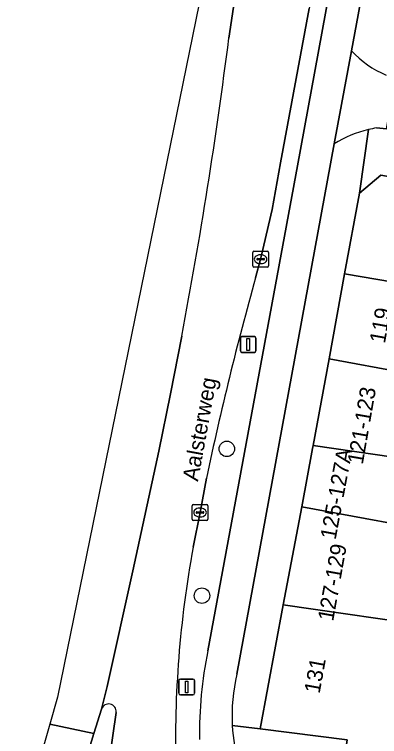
# Model space of a CAD drawing. Extents: x 161838 to 162344, y 381620 to 382160.
# Drawn here: x 161845.08 to 161868.19, y 381676.84 to 381722.46 of the extents above; entities that cross this region are included whole.
import ezdxf

# ---------------------------------------------------------------- set-up
doc = ezdxf.new("R2010")
doc.units = 0
for name, color, linetype in [('IMGEO_Berm_open', 7, 'Continuous'), ('IMGEO_Boom', 7, 'Continuous'), ('IMGEO_Fietspad_gesloten', 7, 'Continuous'), ('IMGEO_Kolk', 7, 'Continuous'), ('IMGEO_Lichtmast', 7, 'Continuous'), ('IMGEO_Openbare_ruimte_label', 7, 'Continuous'), ('IMGEO_OVBaan_gesloten', 7, 'Continuous'), ('IMGEO_Pand', 7, 'Continuous'), ('IMGEO_Pand_nummerreeks', 7, 'Continuous'), ('IMGEO_Rijbaan_lokaal_gesloten', 7, 'Continuous'), ('IMGEO_Rijbaan_lokaal_open', 7, 'Continuous'), ('IMGEO_Verkeerseiland_open', 7, 'Continuous'), ('IMGEO_Voetpad_open', 7, 'Continuous')]:
    doc.layers.add(name, color=color, linetype=linetype)

msp = doc.modelspace()

# ---------------------------------------------------------------- linework, layer by layer
at = {"layer": 'IMGEO_Berm_open'}
for points in [[(161857.316, 381682.246), (161862.987, 381712.892), (161864.774, 381722.548), (161869.854, 381750), (161870.207, 381751.91), (161895.081, 381884.229), (161897.858, 381899.101)], [(161867.182, 381741.481), (161867.15, 381741.313), (161863.721, 381722.825), (161861.927, 381713.087), (161861.385, 381710.143), (161860.718, 381707.24), (161860.66, 381706.996), (161860.336, 381705.821)], [(161857.237, 381693.169), (161856.828, 381690.992), (161856.388, 381688.799)]]:
    msp.add_lwpolyline(points, dxfattribs=at)
for centre, radius, start, end in [((162053.993, 381651.681), 201.083, 164.38075, 168.09298), ((161923.078, 381676.552), 67.805, 169.59407, 181.46627), ((161883.604, 381676.943), 26.817, 168.5945, 180.6234)]:
    msp.add_arc(centre, radius, start, end, dxfattribs=at)
at = {"layer": 'IMGEO_Boom'}
for centre in [(161858.521, 381695.01), (161856.948, 381685.734)]:
    msp.add_circle(centre, 0.489, dxfattribs=at)
at = {"layer": 'IMGEO_Fietspad_gesloten'}
for points in [[(161926.346, 382051.921), (161921.558, 382026.031), (161916.698, 382000), (161897.858, 381899.101), (161895.081, 381884.229), (161870.207, 381751.91), (161869.854, 381750), (161864.774, 381722.548), (161862.987, 381712.892), (161857.316, 381682.246)], [(161859.158, 381680.785), (161865.321, 381714.277), (161866.402, 381720.165), (161871.936, 381750), (161872.236, 381751.615), (161897.095, 381883.929)]]:
    msp.add_lwpolyline(points, dxfattribs=at)
for centre, radius, start, end in [((161883.604, 381676.943), 26.817, 168.5945, 180.6234), ((161870.183, 381678.165), 11.332, 166.6322, 183.1415), ((161870.106, 381678.174), 11.256, 183.2077, 196.1764)]:
    msp.add_arc(centre, radius, start, end, dxfattribs=at)
at = {"layer": 'IMGEO_Kolk'}
for p, q in [((161860.16, 381706.569), (161860.16, 381707.421)), ((161860.235, 381707.495), (161861.087, 381707.495)), ((161861.161, 381707.421), (161861.161, 381706.569)), ((161860.419, 381706.989), (161860.419, 381707.001)), ((161860.857, 381706.952), (161860.459, 381706.952)), ((161860.462, 381707.038), (161860.86, 381707.038)), ((161860.648, 381707.275), (161860.673, 381707.275)), ((161860.903, 381707.001), (161860.903, 381706.989)), ((161861.087, 381706.495), (161860.235, 381706.495)), ((161860.671, 381706.715), (161860.646, 381706.715)), ((161856.328, 381690.566), (161856.328, 381691.418)), ((161856.403, 381691.492), (161857.255, 381691.492)), ((161857.329, 381691.418), (161857.329, 381690.566)), ((161856.587, 381690.986), (161856.587, 381690.998)), ((161857.025, 381690.949), (161856.627, 381690.949)), ((161856.63, 381691.035), (161857.028, 381691.035)), ((161856.816, 381691.272), (161856.841, 381691.272)), ((161857.071, 381690.998), (161857.071, 381690.986)), ((161857.255, 381690.492), (161856.403, 381690.492)), ((161856.839, 381690.712), (161856.814, 381690.712))]:
    msp.add_line(p, q, dxfattribs=at)
for points in [[(161860.16, 381706.569), (161860.16, 381707.421)], [(161860.235, 381707.495), (161861.087, 381707.495)], [(161861.161, 381707.421), (161861.161, 381706.569)], [(161861.087, 381706.495), (161860.235, 381706.495)], [(161856.328, 381690.566), (161856.328, 381691.418)], [(161856.403, 381691.492), (161857.255, 381691.492)], [(161857.329, 381691.418), (161857.329, 381690.566)], [(161857.255, 381690.492), (161856.403, 381690.492)]]:
    msp.add_lwpolyline(points, dxfattribs=at)
for centre, radius, start, end in [((161860.237, 381707.419), 0.0765, 91.552, 178.448), ((161860.237, 381707.419), 0.0765, 91.552, 178.448), ((161861.085, 381707.419), 0.0765, 1.552, 88.448), ((161861.085, 381707.419), 0.0765, 1.552, 88.448), ((161860.459, 381706.998), 0.0403, 85.8775, 175.7526), ((161860.456, 381706.988), 0.0366, 178.938, 274.7102), ((161860.86, 381706.995), 0.043, 264.8664, 352.4533), ((161860.864, 381707), 0.0386, 1.7309, 96.639), ((161860.237, 381706.571), 0.0765, 181.552, 268.448), ((161860.237, 381706.571), 0.0765, 181.552, 268.448), ((161861.085, 381706.571), 0.0765, 271.552, 358.448), ((161861.085, 381706.571), 0.0765, 271.552, 358.448), ((161856.405, 381691.416), 0.0765, 91.552, 178.448), ((161856.405, 381691.416), 0.0765, 91.552, 178.448), ((161857.253, 381691.416), 0.0765, 1.552, 88.448), ((161857.253, 381691.416), 0.0765, 1.552, 88.448), ((161856.627, 381690.995), 0.0403, 85.8775, 175.7526), ((161856.624, 381690.985), 0.0366, 178.938, 274.7102), ((161857.028, 381690.992), 0.043, 264.8664, 352.4533), ((161857.032, 381690.997), 0.0386, 1.7309, 96.639), ((161856.405, 381690.568), 0.0765, 181.552, 268.448), ((161856.405, 381690.568), 0.0765, 181.552, 268.448), ((161857.253, 381690.568), 0.0765, 271.552, 358.448), ((161857.253, 381690.568), 0.0765, 271.552, 358.448)]:
    msp.add_arc(centre, radius, start, end, dxfattribs=at)
for centre, major_axis, ratio, start_param, end_param in [((161860.647, 381706.995), (-0.387, 0.002), 0.722429, 4.712389, 7.853982), ((161860.672, 381706.995), (-0.39, 0.002), 0.717154, 1.570796, 4.712389), ((161856.815, 381690.992), (-0.387, 0.002), 0.722429, 4.712389, 7.853982), ((161856.84, 381690.992), (-0.39, 0.002), 0.717154, 1.570796, 4.712389)]:
    msp.add_ellipse(centre, major_axis=major_axis, ratio=ratio, start_param=start_param, end_param=end_param, dxfattribs=at)
at = {"layer": 'IMGEO_Lichtmast'}
for p, q in [((161859.376, 381701.208), (161859.376, 381702.008)), ((161859.376, 381702.008), (161859.376, 381701.208)), ((161859.476, 381702.108), (161860.266, 381702.108)), ((161860.266, 381702.108), (161859.476, 381702.108)), ((161860.366, 381702.008), (161860.366, 381701.208)), ((161860.366, 381701.208), (161860.366, 381702.008)), ((161860.266, 381701.108), (161859.476, 381701.108)), ((161859.476, 381701.108), (161860.266, 381701.108)), ((161855.585, 381680.469), (161856.375, 381680.469)), ((161856.375, 381680.469), (161855.585, 381680.469)), ((161855.485, 381679.569), (161855.485, 381680.369)), ((161855.485, 381680.369), (161855.485, 381679.569)), ((161856.475, 381680.369), (161856.475, 381679.569)), ((161856.475, 381679.569), (161856.475, 381680.369)), ((161856.375, 381679.469), (161855.585, 381679.469)), ((161855.585, 381679.469), (161856.375, 381679.469))]:
    msp.add_line(p, q, dxfattribs=at)
for points in [[(161859.796, 381701.983), (161859.946, 381701.983), (161859.946, 381701.233), (161859.796, 381701.233), (161859.796, 381701.983)], [(161855.905, 381680.344), (161856.055, 381680.344), (161856.055, 381679.594), (161855.905, 381679.594), (161855.905, 381680.344)]]:
    msp.add_lwpolyline(points, dxfattribs=at)
for centre, start, end in [((161859.476, 381702.008), 90, 180), ((161859.476, 381702.008), 90, 180), ((161860.266, 381702.008), 0, 90), ((161860.266, 381702.008), 360, 90), ((161859.476, 381701.208), 180, 270), ((161859.476, 381701.208), 180, 270), ((161860.266, 381701.208), 270, 0), ((161860.266, 381701.208), 270, 0), ((161855.585, 381680.369), 90, 180), ((161855.585, 381680.369), 90, 180), ((161856.375, 381680.369), 0, 90), ((161856.375, 381680.369), 360, 90), ((161855.585, 381679.569), 180, 270), ((161855.585, 381679.569), 180, 270), ((161856.375, 381679.569), 270, 0), ((161856.375, 381679.569), 270, 0)]:
    msp.add_arc(centre, 0.1, start, end, dxfattribs=at)
at = {"layer": 'IMGEO_OVBaan_gesloten'}
for points in [[(161858.651, 381720.96), (161859.425, 381726.158), (161861.132, 381736.231), (161869.606, 381781.344), (161897.211, 381928.16), (161915.531, 382025.949), (161915.767, 382027.092), (161920.812, 382054.098), (161923.657, 382069.694), (161925.944, 382081.248), (161931.886, 382108.929), (161933.831, 382119.131), (161934.302, 382121.796), (161934.443, 382123.117), (161933.101, 382124.399), (161916.93, 382035.129), (161911.481, 382007.357), (161883.773, 381866.122), (161869.795, 381786.79), (161847.814, 381679.325), (161847.327, 381677.629)], [(161847.327, 381677.629), (161850.099, 381677.022), (161850.6, 381678.563), (161850.947, 381680.009), (161852.565, 381687.299), (161854.222, 381694.86), (161854.959, 381698.492), (161855.668, 381702.138)]]:
    msp.add_lwpolyline(points, dxfattribs=at)
msp.add_arc((161552.98, 381759.757), 308.123, 349.22229, 352.7665, dxfattribs=at)
at = {"layer": 'IMGEO_Pand'}
for points in [[(161865.976, 381706.071), (161875.017, 381704.529), (161884.134, 381702.846), (161883.394, 381698.839), (161888.293, 381698.163), (161889.03, 381703.608), (161889.701, 381708.562), (161868.259, 381712.301), (161866.911, 381711.167)], [(161864.991, 381700.701), (161879.355, 381698.049), (161879.861, 381700.795), (161874.51, 381701.783), (161875.017, 381704.529), (161865.976, 381706.071)], [(161879.355, 381698.049), (161864.991, 381700.701), (161863.987, 381695.233), (161874.156, 381693.76), (161874.552, 381695.908), (161879.868, 381695.095), (161880.378, 381697.86)], [(161874.156, 381693.76), (161863.987, 381695.233), (161863.949, 381695.025), (161863.26, 381691.359), (161882.969, 381687.722), (161883.096, 381688.415), (161883.357, 381689.827), (161877.499, 381690.634), (161877.82, 381692.85), (161875.023, 381693.255), (161874.094, 381693.426)], [(161892.652, 381687.039), (161883.096, 381688.415), (161882.969, 381687.722), (161863.26, 381691.359), (161862.095, 381685.158), (161872.016, 381683.722), (161872.074, 381684.036), (161876.798, 381683.292), (161882.189, 381682.256), (161885.412, 381681.832), (161886.558, 381681.681), (161890.01, 381681.227), (161891.585, 381681.02)], [(161886.558, 381681.681), (161885.412, 381681.832), (161882.189, 381682.256), (161876.798, 381683.292), (161872.074, 381684.036), (161872.016, 381683.722), (161862.095, 381685.158), (161860.622, 381677.32), (161866.135, 381676.635), (161866.008, 381675.715), (161870.39, 381674.905), (161877.184, 381673.822), (161882.832, 381672.922), (161885.465, 381672.502), (161885.826, 381675.533), (161886.077, 381677.646)]]:
    msp.add_lwpolyline(points, close=True, dxfattribs=at)
at = {"layer": 'IMGEO_Rijbaan_lokaal_gesloten'}
for points in [[(161918.789, 382041.718), (161915.767, 382027.092), (161915.531, 382025.949), (161897.211, 381928.16), (161869.606, 381781.344), (161861.132, 381736.231), (161859.425, 381726.158), (161858.651, 381720.96)], [(161860.336, 381705.821), (161860.66, 381706.996), (161860.718, 381707.24), (161861.385, 381710.143), (161861.927, 381713.087), (161863.721, 381722.825)], [(161855.668, 381702.138), (161854.959, 381698.492), (161854.222, 381694.86), (161852.565, 381687.299), (161850.947, 381680.009), (161850.6, 381678.563)], [(161856.388, 381688.799), (161856.828, 381690.992), (161857.237, 381693.169)], [(161851.509, 381678.364), (161851.12, 381675.59), (161850.65, 381672.6), (161850.628, 381672.471), (161850.018, 381669.176), (161857.436, 381667.509)], [(161847.327, 381677.629), (161845.081, 381669.8), (161847.726, 381669.709), (161848.769, 381672.848), (161848.829, 381673.033), (161849.717, 381675.784), (161850.099, 381677.022), (161847.327, 381677.629)]]:
    msp.add_lwpolyline(points, dxfattribs=at)
for centre, radius, start, end in [((161552.98, 381759.757), 308.123, 349.22229, 352.7665), ((162053.993, 381651.681), 201.083, 164.38075, 168.09298), ((161923.078, 381676.552), 67.805, 169.59407, 181.46627), ((161851.048, 381678.432), 0.466, 351.5731, 163.7299)]:
    msp.add_arc(centre, radius, start, end, dxfattribs=at)
at = {"layer": 'IMGEO_Rijbaan_lokaal_open'}
for points in [[(161866.402, 381720.165), (161865.321, 381714.277)], [(161867.989, 381715.284), (161868.626, 381715.237), (161869.225, 381718.514)]]:
    msp.add_lwpolyline(points, dxfattribs=at)
for centre, radius, start, end in [((161871.05, 381724.49), 6.349, 222.9381, 247.3886), ((161869.087, 381708.336), 7.034, 103.2185, 122.3752), ((161869.008, 381708.739), 6.624, 98.8455, 103.342)]:
    msp.add_arc(centre, radius, start, end, dxfattribs=at)
at = {"layer": 'IMGEO_Verkeerseiland_open'}
for points in [[(161850.6, 381678.563), (161850.099, 381677.022), (161849.717, 381675.784)], [(161851.12, 381675.59), (161851.509, 381678.364)]]:
    msp.add_lwpolyline(points, dxfattribs=at)
msp.add_arc((161851.048, 381678.432), 0.466, 351.5731, 163.7299, dxfattribs=at)
at = {"layer": 'IMGEO_Voetpad_open'}
for points in [[(161907.39, 381938.834), (161899.866, 381898.705), (161897.095, 381883.929), (161872.236, 381751.615), (161871.936, 381750), (161866.402, 381720.165)], [(161867.479, 381715.184), (161866.911, 381711.167), (161868.259, 381712.301), (161889.701, 381708.562), (161890.618, 381708.428), (161896.772, 381707.527), (161902.202, 381706.732), (161907.63, 381705.938), (161913.399, 381705.093), (161916.016, 381704.682), (161918.308, 381704.376), (161918.428, 381705.281), (161922.044, 381704.799), (161922.127, 381705.725), (161922.319, 381707.479)], [(161866.911, 381711.167), (161867.479, 381715.184)], [(161868.939, 381715.193), (161868.626, 381715.237), (161867.989, 381715.284)], [(161865.321, 381714.277), (161859.158, 381680.785)], [(161858.868, 381677.544), (161860.622, 381677.32), (161862.095, 381685.158), (161863.26, 381691.359), (161863.949, 381695.025), (161863.987, 381695.233), (161864.991, 381700.701), (161865.976, 381706.071), (161866.911, 381711.167)], [(161980.874, 381650.011), (161978.924, 381650.27), (161977.386, 381650.474), (161946.525, 381654.568), (161944.516, 381654.835), (161906.825, 381659.836), (161902.061, 381660.536), (161897.485, 381661.208), (161892.748, 381661.903), (161887.786, 381662.632), (161881.751, 381664.382), (161876.207, 381665.989), (161865.106, 381669.207), (161866.008, 381675.715), (161866.135, 381676.635), (161860.622, 381677.32), (161858.868, 381677.544)]]:
    msp.add_lwpolyline(points, dxfattribs=at)
for centre, radius, start, end in [((161871.05, 381724.49), 6.349, 222.9381, 247.3886), ((161869.087, 381708.336), 7.034, 103.2185, 122.3752), ((161869.008, 381708.739), 6.624, 98.8455, 103.342), ((161870.183, 381678.165), 11.332, 166.6322, 183.1415), ((161870.106, 381678.174), 11.256, 183.2077, 196.1764)]:
    msp.add_arc(centre, radius, start, end, dxfattribs=at)

# ---------------------------------------------------------------- texts
at = {"layer": 'IMGEO_Openbare_ruimte_label'}
msp.add_text('Aalsterweg', height=1, rotation=79.6337, dxfattribs=at).set_placement((161856.692, 381692.922))
at = {"layer": 'IMGEO_Pand_nummerreeks'}
for s, rotation, p in [('119', 79.8201, (161868.524, 381701.633)), ('121-123', 80.0307, (161867.122, 381693.99)), ('125-127A', 79.3547, (161865.403, 381689.231)), ('127-129', 79.8073, (161865.249, 381684.079)), ('131', 79.6354, (161864.39, 381679.513))]:
    msp.add_text(s, height=1, rotation=rotation, dxfattribs=at).set_placement(p)

doc.saveas('drawing.dxf')
